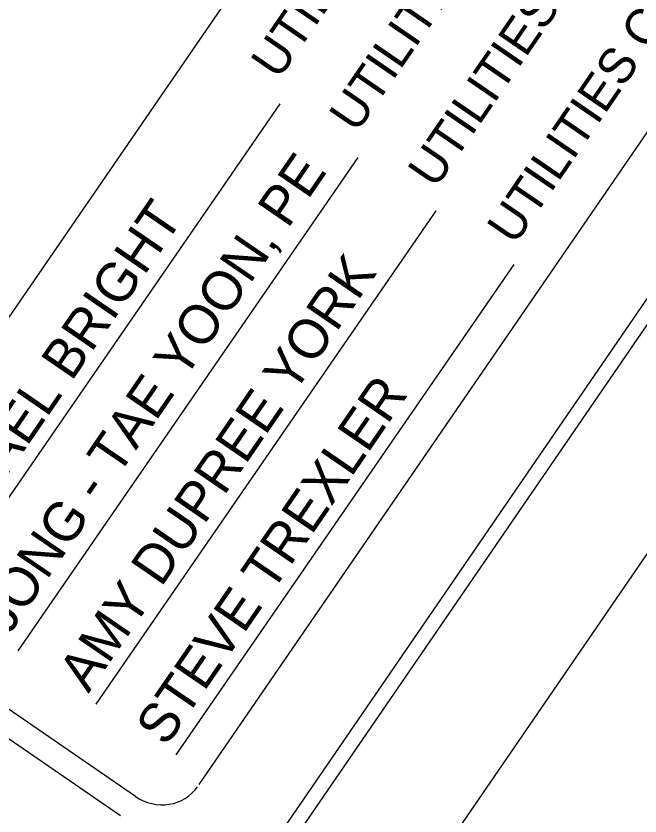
# Model space of a CAD drawing. Extents: x 1638787 to 1643250, y 391480 to 396306.
# Drawn here: x 1642723.5 to 1642982.6, y 394318.6 to 394651 of the extents above; entities that cross this region are included whole.
import ezdxf

# ---------------------------------------------------------------- set-up
doc = ezdxf.new("R2010")
doc.units = 0
for name, color, linetype in [('Sheet Plot Border Inside CELL', 7, 'Continuous'), ('Sheet Plot Border Outside CELL', 7, 'Continuous'), ('UC Title Plan Sheet 34 CELL', 7, 'Continuous')]:
    doc.layers.add(name, color=color, linetype=linetype)

msp = doc.modelspace()

# ---------------------------------------------------------------- linework, layer by layer
at = {"layer": 'Sheet Plot Border Inside CELL'}
msp.add_lwpolyline([(1640937.67, 391536.41), (1643199.64, 394834.94), (1641111.26, 396267.04), (1638849.29, 392968.51)], close=True, dxfattribs=at)
at = {"layer": 'Sheet Plot Border Outside CELL'}
msp.add_lwpolyline([(1641072.93, 396306.42), (1638787.21, 392973.25), (1640964.44, 391480.22), (1643250.15, 394813.39)], close=True, dxfattribs=at)
at = {"layer": 'UC Title Plan Sheet 34 CELL'}
for p, q in [((1642644.51, 394415.23), (1642989.59, 394917.51)), ((1642799.61, 394331.71), (1643123.65, 394803.96)), ((1642691.89, 394409.44), (1642833.19, 394614.51)), ((1642724.33, 394387.26), (1642865.6, 394592.29)), ((1642756.78, 394365.08), (1642898.01, 394570.06)), ((1642790.06, 394344.11), (1642930.42, 394547.84)), ((1642773.12, 394326.8), (1642492.49, 394519.74)), ((1642766.83, 394318.69), (1642486.81, 394511.29))]:
    msp.add_line(p, q, dxfattribs=at)
msp.add_lwpolyline([(1641155.22, 391864.48), (1643164.05, 394793.87)], dxfattribs=at)
msp.add_ellipse((1642783.2, 394341.48), major_axis=(-15.61, 10.71), ratio=0.941469, start_param=1.570198, end_param=3.141359, dxfattribs=at)

# ---------------------------------------------------------------- texts
for s, height, p in [('UTILITIES REGIONAL ENGINEER', 14.8358, (1642832.5, 394624.19)), ('UTILITIES AREA COORDINATOR', 14.8358, (1642897.65, 394578.89)), ('UTILITIES ENGINEER', 14.8358, (1642864.94, 394602.01)), ('UTILITIES COORDINATOR', 14.8358, (1642930.52, 394555.37)), ('JONG - TAE YOON, PE', 16.3193, (1642720.47, 394393.4)), ('MICHAEL BRIGHT', 16.3193, (1642688.22, 394413.9)), ('AMY DUPREE YORK', 16.3193, (1642753.58, 394369.38)), ('STEVE TREXLER', 16.3193, (1642785.79, 394347.02))]:
    msp.add_text(s, height=height, rotation=55.5455, dxfattribs=at).set_placement(p)

doc.saveas('drawing.dxf')
